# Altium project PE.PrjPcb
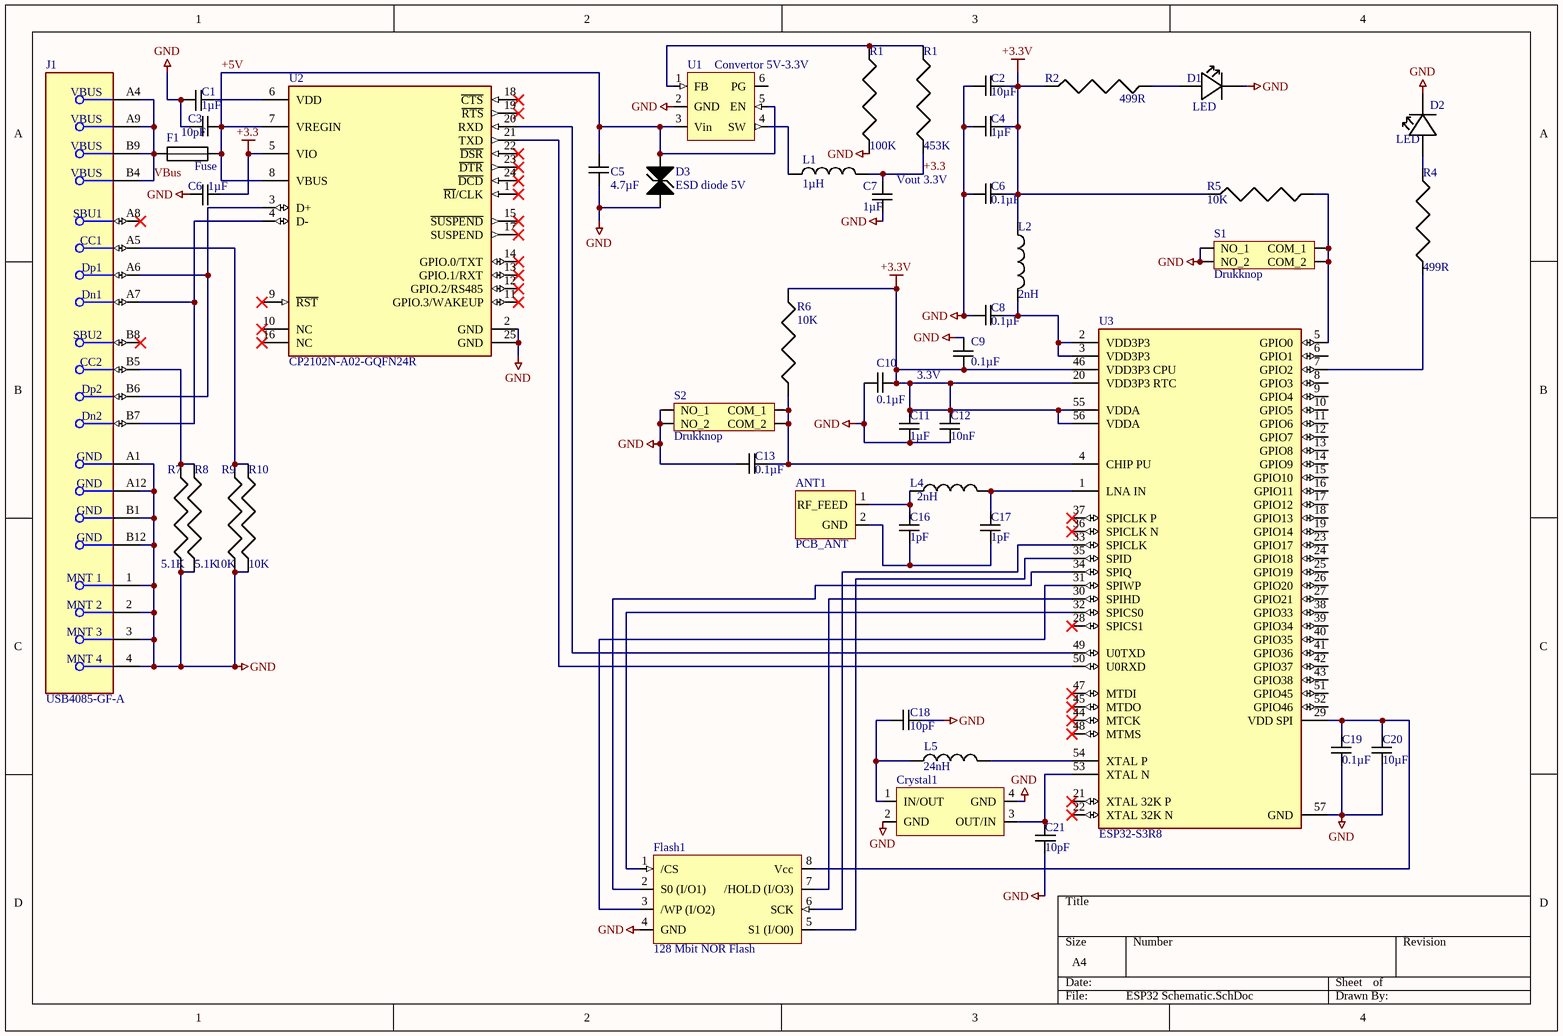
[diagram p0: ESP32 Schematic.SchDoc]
1 sheet, 47 parts. Net scope: global (net labels, ports and power ports of the same name join across sheets).
Board file: PCB-v1.PcbDoc

## Sheet ESP32 Schematic.SchDoc
size A4; SheetNumber: 1; SheetTotal: 1

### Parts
(Parts that share a designator on the sheet are numbered #1, #2 ... from top to bottom, then left to right.)
ANT1  PCB_ANT  [Antenne // RFANT5220110A0T]
C1  1µF  [CAP_General_0603]
C2  10µF  [CAP_General_0603]
C3  10pF  [CAP_General_0603]
C4  1µF  [CAP_General_0603]
C5  4.7µF  [CAP_General_0603]
C6#1  1µF  [CAP_General_0603]
C6#2  0.1µF  [CAP_General_0603]
C7  1µF  [CAP_General_0603]
C8  0.1µF  [CAP_General_0603]
C9  0.1µF  [CAP_General_0603]
C10  0.1µF  [CAP_General_0603]
C11  1µF  [CAP_General_0603]
C12  10nF  [CAP_General_0603]
C13  0.1µF  [CAP_General_0603]
C16  1pF  [CAP_General_0603]
C17  1pF  [CAP_General_0603]
C18  10pF  [CAP_General_0603]
C19  0.1µF  [CAP_General_0603]
C20  10µF  [CAP_General_0603]
C21  10pF  [CAP_General_0603]
Crystal1  Crystal  [Crystal // ECS­400­8­47B2­CKM­TR]  (value not drawn)
D1  LED  [LED // KRDELPS1.22-UIVG-46-H3Q4-XX]
D2  LED  [LED // KRDELPS1.22-UIVG-46-H3Q4-XX]
D3  ESD diode 5V  [ESD diode 5V // SMF5.0A]
F1  Fuse  [Fuse // 0603L050SLYR]
Flash1  128 Mbit NOR Flash  [128 Mbit NOR Flash // AT25QF128A-MHB-T]
J1  USB4085-GF-A  [USB-C connector // USB4085-GF-A]
L1  1µH  [Inductor 1µH // MLP2520H1R0MT0S1]
L2  2nH  [Inductor 2nH // MLG1005S2N0BTD25]
L4  2nH  [Inductor 2nH // MLG1005S2N0BTD25]
L5  24nH  [Inductor 24 nH // 36501J24NJTDG]
R1#1  100K  [RES_100K_0603]
R1#2  453K  [RES_453K_0603]
R2  499R  [RES_499R_0603]
R4  499R  [RES_499R_0603]
R5  10K  [RES_10K_0603_1]
R6  10K  [RES_10K_0603_1]
R7  5.1K  [RES_5.1K_0603]
R8  5.1K  [RES_5.1K_0603]
R9  10K  [RES_10K_0603_1]
R10  10K  [RES_10K_0603_1]
S1  Drukknop  [Tactile Switches // FSM4JSMAATR]
S2  Drukknop  [Tactile Switches // FSM4JSMAATR]
U1  Convertor 5V-3.3V  [CONVERTOR // TLV62569APDRLR]
U2  CP2102N-A02-GQFN24R  [USB Bridge // CP2102N-A02-GQFN24R]
U3  ESP32-S3R8  [FP-ESP32-S3R8]

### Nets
+3.3: C6#1.1 C7.2 L1.2 R1#2.2 U2.5(VIO)
+3.3V: C2.2 C4.2 C6#2.2 C9.1 C10.2 C11.2 C12.2 L2.1 R2.1 R5.1 R6.2 U3.20(VDD3P3_RTC) U3.46(VDD3P3_CPU) U3.55(VDDA) U3.56(VDDA)
GND: C1.2 C2.1 C3.1 C4.1 C5.1 C6#1.2 C6#2.1 C7.1 C8.1 C9.2 C10.1 C11.1 C12.1 C13.1 C18.2 C19.1 C20.1 C21.2 Crystal1.2(GND) Crystal1.4(GND) D1.2 D2.2 D3.2 Flash1.4(GND) J1.1(MNT_1) J1.2(MNT_2) J1.3(MNT_3) J1.4(MNT_4) J1.A1(GND) J1.A12(GND) J1.B1(GND) J1.B12(GND) R1#1.1 R7.1 R8.1 R9.1 R10.1 S1.3(NO_1) S1.4(NO_2) S2.3(NO_1) S2.4(NO_2) U1.2(GND) U2.2(GND) U2.25(GND) U3.57(GND)
+5V: C3.2 C5.2 D3.1 F1.2 U1.3(Vin) U1.5(EN) U2.7(VREGIN) U2.8(VBUS)
VBus: F1.1 J1.A4(VBUS) J1.A9(VBUS) J1.B4(VBUS) J1.B9(VBUS)
NetANT1_1: ANT1.1(RF_FEED) C16.2 L4.1
NetANT1_2: ANT1.2(GND) C16.1 C17.1
NetC1_1: C1.1 U2.6(VDD)
NetC8_2: C8.2 L2.2 U3.2(VDD3P3) U3.3(VDD3P3)
NetC13_2: C13.2 R6.1 S2.1(COM_1) S2.2(COM_2) U3.4(CHIP_PU)
NetC17_2: C17.2 L4.2 U3.1(LNA_IN)
NetC18_1: C18.1 Crystal1.1(IN/OUT) L5.1
NetC19_2: C19.2 C20.2 Flash1.8(Vcc) U3.29(VDD_SPI)
NetC21_1: C21.1 Crystal1.3(OUT/IN) U3.53(XTAL_N)
NetD1_1: D1.1 R2.2
NetD2_1: D2.1 R4.2
NetFlash1_1: Flash1.1(/CS) U3.32(SPICS0)
NetFlash1_2: Flash1.2(S0_(I/O1)) U3.34(SPIQ)
NetFlash1_3: Flash1.3(/WP_(I/O2)) U3.31(SPIWP)
NetFlash1_5: Flash1.5(S1_(I/O0)) U3.35(SPID)
NetFlash1_6: Flash1.6(SCK) U3.33(SPICLK)
NetFlash1_7: Flash1.7(/HOLD_(I/O3)) U3.30(SPIHD)
NetJ1_A5: J1.A5(CC1) R9.2 R10.2
NetJ1_A6: J1.A6(Dp1) J1.B6(Dp2) U2.3(D+)
NetJ1_A7: J1.A7(Dn1) J1.B7(Dn2) U2.4(D-)
NetJ1_B5: J1.B5(CC2) R7.2 R8.2
NetL1_1: L1.1 U1.4(SW)
NetL5_2: L5.2 U3.54(XTAL_P)
NetR1#1_2: R1#1.2 R1#2.1 U1.1(FB)
NetR4_1: R4.1 U3.7(GPIO2)
NetR5_2: R5.2 S1.1(COM_1) S1.2(COM_2) U3.5(GPIO0)
NetU2_20: U2.20(RXD) U3.49(U0TXD)
NetU2_21: U2.21(TXD) U3.50(U0RXD)

Not connected (* = marked no-connect by the designer): J1 A8(SBU1)* B8(SBU2)*; U1 6(PG); U2 1(~{RI}/CLK)* 9(~{RST})* 10(NC)* 11(GPIO.3/WAKEUP)* 12(GPIO.2/RS485)* 13(GPIO.1/RXT)* 14(GPIO.0/TXT)* 15(~{SUSPEND})* 16(NC)* 17(SUSPEND)* 18(~{CTS})* 19(~{RTS})* 22(~{DSR})* 23(~{DTR})* 24(~{DCD})*; U3 6(GPIO1) 8(GPIO3) 9(GPIO4) 10(GPIO5) 11(GPIO6) 12(GPIO7) 13(GPIO8) 14(GPIO9) 15(GPIO10) 16(GPIO11) 17(GPIO12) 18(GPIO13) 19(GPIO14) 21(XTAL_32K_P)* 22(XTAL_32K_N)* 23(GPIO17) 24(GPIO18) 25(GPIO19) 26(GPIO20) 27(GPIO21) 28(SPICS1)* 36(SPICLK_N)* 37(SPICLK_P)* 38(GPIO33) 39(GPIO34) 40(GPIO35) 41(GPIO36) 42(GPIO37) 43(GPIO38) 44(MTCK)* 45(MTDO)* 47(MTDI)* 48(MTMS)* 51(GPIO45) 52(GPIO46)

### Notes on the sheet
- (near C7) Vout 3.3V
- 3.3V

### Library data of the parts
ANT1 = Antenne // RFANT5220110A0T
C1-C5 C6#1 C6#2 C7-C13 C16-C21 = CAP_General_0603: Capacitor SMD 0603 ?pF
Crystal1 = Crystal // ECS­400­8­47B2­CKM­TR
D1 D2 = LED // KRDELPS1.22-UIVG-46-H3Q4-XX
D3 = ESD diode 5V // SMF5.0A
F1 = Fuse // 0603L050SLYR
Flash1 = 128 Mbit NOR Flash // AT25QF128A-MHB-T
J1 = USB-C connector // USB4085-GF-A: CONN RCPT USB2.0 TYPE C 24POS RA; Gender: Receptacle; Number of Positions: 16
L1 = Inductor 1µH // MLP2520H1R0MT0S1
L2 L4 = Inductor 2nH // MLG1005S2N0BTD25
L5 = Inductor 24 nH // 36501J24NJTDG
R1#1 = RES_100K_0603: Resistor SMD 0603 100K
R1#2 = RES_453K_0603: Resistor SMD 0603 453K
R2 R4 = RES_499R_0603: Resistor SMD 0603 499R
R5-R10 = RES_10K_0603_1: Resistor SMD 0603 10K
S1 S2 = Tactile Switches // FSM4JSMAATR
U1 = Convertor // TLV62569APDRLR
U2 = USB Bridge // CP2102N-A02-GQFN24R: IC USB TO UART BRIDGE QFN24; Manufacturer Lifecycle Status: FULL PRODUCTION; NexarPartId: 99772192; Max Junction Temperature (Tj): 105°C; Min Supply Voltage: 1.71V; Max Supply Voltage: 3.6V; Number of Digital IO: 4; Interface: I2C, RS-485, UART, USB
U3 = ESP32-S3: ESP32-S3R8 RF System on a Chip - SoC SMD IC, Dual-Core MCU, Wi-Fi 2.4G BLE 5.0 Combo; NexarPartId: 118292493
